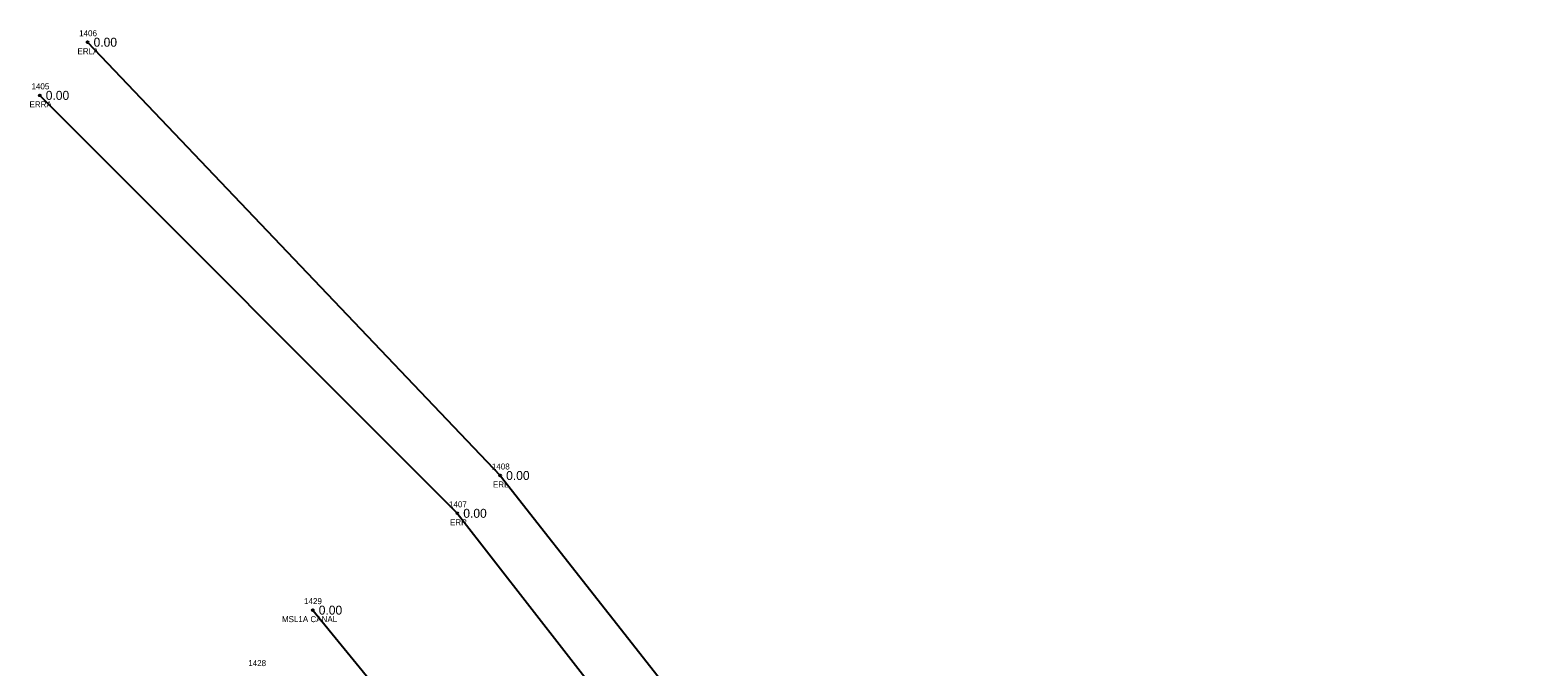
# Model space of a CAD drawing. Extents: x 1969805 to 1970312, y 796761 to 797393.
# Drawn here: x 1969804.8 to 1970056.1, y 797286.8 to 797393 of the extents above; entities that cross this region are included whole.
import ezdxf

# ---------------------------------------------------------------- set-up
doc = ezdxf.new("R2010")
doc.units = 0
for name, color, linetype in [('RD_EX_Misc', 7, 'Continuous'), ('RD_EX_Misc_txCode', 7, 'Continuous'), ('RD_EX_Road', 7, 'Continuous'), ('RD_EX_Road_txCode', 7, 'Continuous'), ('RD_EX_TX_Misc_ELEV', 7, 'Continuous'), ('RD_EX_TX_Road_ELEV', 7, 'Continuous'), ('RD_SMD_Locator', 7, 'Continuous')]:
    doc.layers.add(name, color=color, linetype=linetype)

msp = doc.modelspace()

# ---------------------------------------------------------------- linework, layer by layer
at = {"layer": 'RD_EX_Misc'}
msp.add_lwpolyline([(1969851.9, 797296.28), (1969923.81, 797208.31), (1970003.56, 797143.68), (1970066.45, 797065.71), (1970139.5, 796988.23), (1970200.74, 796906.81), (1970275.73, 796810.69)], dxfattribs=at)
at = {"layer": 'RD_EX_Road'}
for points in [[(1969814.38, 797390.94), (1969883.13, 797318.72), (1969937.65, 797249.39), (1969950.29, 797234.74), (1969990.29, 797195.4), (1970023.69, 797160.38), (1970092.97, 797083.8), (1970155.67, 797004.32), (1970228.35, 796927.95), (1970307.3, 796837.78)], [(1969806.41, 797382.08), (1969875.99, 797312.42), (1969930.44, 797242.42), (1969942.97, 797227.29), (1969983.6, 797189.03), (1970017.23, 797153.7), (1970084.26, 797077.69), (1970150.07, 796998.74), (1970221.42, 796920.94), (1970298.76, 796831.54)]]:
    msp.add_lwpolyline(points, dxfattribs=at)
at = {"layer": 'RD_SMD_Locator'}
for centre in [(1969814.38, 797390.94), (1969806.41, 797382.08), (1969883.13, 797318.72), (1969875.99, 797312.42), (1969851.9, 797296.28)]:
    msp.add_circle(centre, 0.15, dxfattribs=at)

# ---------------------------------------------------------------- texts
at = {"layer": 'RD_EX_Misc_txCode'}
for s, p in [('1429', (1969850.45, 797297.28)), ('MSL1A CANAL', (1969846.76, 797294.28)), ('1428', (1969841.15, 797286.95))]:
    msp.add_text(s, height=1, dxfattribs=at).set_placement(p)
at = {"layer": 'RD_EX_Road_txCode'}
for s, p in [('1406', (1969812.97, 797391.94)), ('ERLA', (1969812.69, 797388.94)), ('1405', (1969805.03, 797383.08)), ('ERRA', (1969804.7, 797380.08)), ('1408', (1969881.75, 797319.72)), ('ERL', (1969881.93, 797316.72)), ('1407', (1969874.61, 797313.42)), ('ERR', (1969874.77, 797310.42))]:
    msp.add_text(s, height=1, dxfattribs=at).set_placement(p)
at = {"layer": 'RD_EX_TX_Misc_ELEV'}
msp.add_text('0.00', height=1.5, dxfattribs=at).set_placement((1969852.9, 797295.53))
at = {"layer": 'RD_EX_TX_Road_ELEV'}
for p in [(1969815.38, 797390.19), (1969807.41, 797381.33), (1969884.13, 797317.97), (1969876.99, 797311.67)]:
    msp.add_text('0.00', height=1.5, dxfattribs=at).set_placement(p)

doc.saveas('drawing.dxf')
